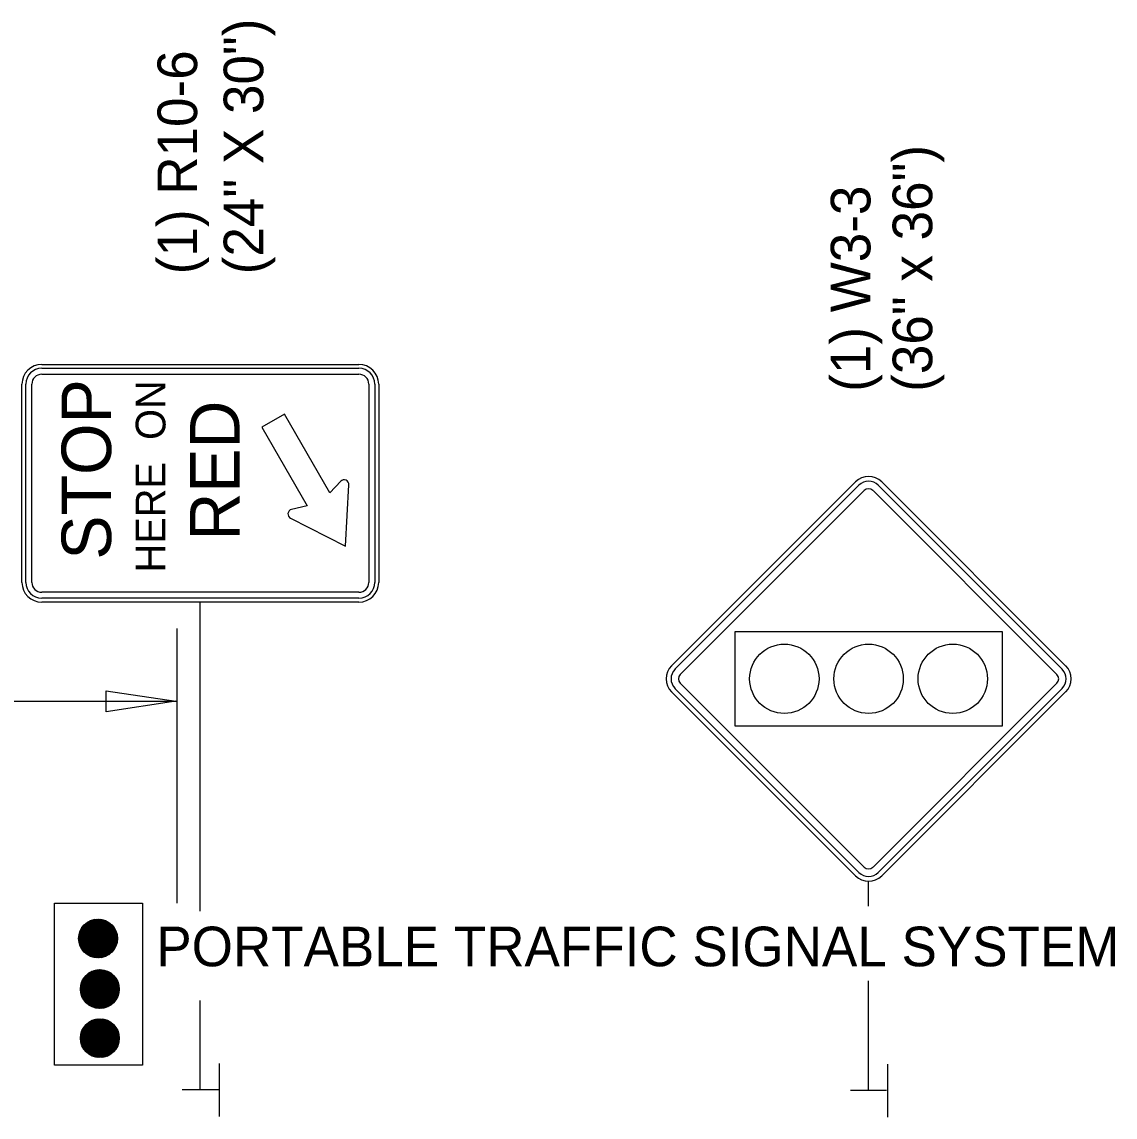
# Model space of a CAD drawing. Extents: x 1926586 to 1930787, y 596452 to 599566.
# Drawn here: x 1928013.4 to 1928178.9, y 598956.9 to 599122.6 of the extents above; entities that cross this region are included whole.
import ezdxf

# ---------------------------------------------------------------- set-up
doc = ezdxf.new("R2010")
doc.units = 0
for name, color, linetype in [('Default', 7, 'Continuous'), ('P_TC_Signs_Permanent', 7, 'Continuous'), ('R_Border', 7, 'Continuous')]:
    doc.layers.add(name, color=color, linetype=linetype)

msp = doc.modelspace()

# ---------------------------------------------------------------- linework, layer by layer
at = {"layer": 'Default'}
for p, q in [((1928036.82, 599030.83), (1928036.82, 598989.25)), ((1928026.16, 599018.22), (1928026.16, 599021.38)), ((1928026.16, 599021.38), (1928036.71, 599019.8)), ((1927973.15, 599019.8), (1928036.82, 599019.8)), ((1928036.71, 599019.8), (1928026.16, 599018.22)), ((1928021.98, 598983.77), (1928025.06, 598986.84)), ((1928021.98, 598983.94), (1928024.88, 598986.84)), ((1928021.99, 598984.13), (1928024.69, 598986.83)), ((1928022, 598983.6), (1928025.23, 598986.83)), ((1928022.01, 598984.34), (1928024.49, 598986.81)), ((1928022.02, 598983.44), (1928025.39, 598986.81)), ((1928022.05, 598983.29), (1928025.54, 598986.78)), ((1928022.06, 598984.56), (1928024.26, 598986.77)), ((1928022.08, 598983.14), (1928025.68, 598986.74)), ((1928022.12, 598983), (1928025.82, 598986.7)), ((1928022.12, 598984.81), (1928024.01, 598986.7)), ((1928022.17, 598982.87), (1928025.96, 598986.66)), ((1928022.22, 598982.74), (1928026.09, 598986.6)), ((1928022.24, 598985.11), (1928023.72, 598986.59)), ((1928022.28, 598982.61), (1928026.21, 598986.55)), ((1928022.34, 598982.49), (1928026.33, 598986.48)), ((1928022.41, 598982.38), (1928026.45, 598986.42)), ((1928022.46, 598985.5), (1928023.32, 598986.37)), ((1928022.48, 598982.27), (1928026.56, 598986.35)), ((1928022.55, 598982.16), (1928026.66, 598986.27)), ((1928022.63, 598982.06), (1928026.76, 598986.2)), ((1928022.71, 598981.96), (1928026.86, 598986.11)), ((1928022.8, 598981.87), (1928026.96, 598986.03)), ((1928022.89, 598981.78), (1928027.05, 598985.94)), ((1928022.98, 598981.69), (1928027.13, 598985.84)), ((1928023.08, 598981.61), (1928027.22, 598985.74)), ((1928023.18, 598981.53), (1928027.3, 598985.64)), ((1928023.29, 598981.45), (1928027.37, 598985.53)), ((1928023.4, 598981.38), (1928027.44, 598985.42)), ((1928023.52, 598981.32), (1928027.51, 598985.31)), ((1928023.63, 598981.26), (1928027.57, 598985.19)), ((1928023.76, 598981.2), (1928027.62, 598985.07)), ((1928023.89, 598981.15), (1928027.68, 598984.94)), ((1928024.02, 598981.1), (1928027.72, 598984.8)), ((1928024.16, 598981.06), (1928027.76, 598984.66)), ((1928024.31, 598981.03), (1928027.8, 598984.52)), ((1928024.46, 598981), (1928027.83, 598984.36)), ((1928024.62, 598980.98), (1928027.85, 598984.2)), ((1928024.79, 598980.96), (1928027.86, 598984.04)), ((1928024.97, 598980.96), (1928027.86, 598983.86)), ((1928025.16, 598980.97), (1928027.85, 598983.67)), ((1928025.36, 598980.99), (1928027.83, 598983.46)), ((1928025.58, 598981.04), (1928027.79, 598983.24)), ((1928025.83, 598981.11), (1928027.72, 598982.99)), ((1928026.13, 598981.22), (1928027.6, 598982.69)), ((1928026.53, 598981.44), (1928027.39, 598982.3)), ((1928022.25, 598976.11), (1928025.33, 598979.18)), ((1928022.25, 598976.29), (1928025.15, 598979.18)), ((1928022.26, 598976.47), (1928024.96, 598979.18)), ((1928022.27, 598975.94), (1928025.5, 598979.17)), ((1928022.28, 598976.68), (1928024.76, 598979.15)), ((1928022.29, 598975.78), (1928025.66, 598979.15)), ((1928022.32, 598975.63), (1928025.81, 598979.12)), ((1928022.32, 598976.9), (1928024.53, 598979.11)), ((1928022.35, 598975.48), (1928025.95, 598979.08)), ((1928022.39, 598975.34), (1928026.09, 598979.04)), ((1928022.39, 598977.15), (1928024.28, 598979.04)), ((1928022.44, 598975.21), (1928026.23, 598979)), ((1928022.49, 598975.08), (1928026.36, 598978.94)), ((1928022.51, 598977.45), (1928023.99, 598978.93)), ((1928022.55, 598974.95), (1928026.48, 598978.89)), ((1928022.61, 598974.83), (1928026.6, 598978.83)), ((1928022.67, 598974.72), (1928026.71, 598978.76)), ((1928022.72, 598977.84), (1928023.59, 598978.71)), ((1928022.75, 598974.61), (1928026.82, 598978.69)), ((1928022.82, 598974.5), (1928026.93, 598978.61)), ((1928022.9, 598974.4), (1928027.03, 598978.54)), ((1928022.98, 598974.3), (1928027.13, 598978.45)), ((1928023.07, 598974.21), (1928027.23, 598978.37)), ((1928023.16, 598974.12), (1928027.32, 598978.28)), ((1928023.25, 598974.03), (1928027.4, 598978.18)), ((1928023.35, 598973.95), (1928027.49, 598978.08)), ((1928023.45, 598973.87), (1928027.56, 598977.98)), ((1928023.56, 598973.8), (1928027.64, 598977.87)), ((1928023.67, 598973.73), (1928027.71, 598977.76)), ((1928023.78, 598973.66), (1928027.78, 598977.65)), ((1928023.9, 598973.6), (1928027.84, 598977.53)), ((1928024.03, 598973.54), (1928027.89, 598977.41)), ((1928024.16, 598973.49), (1928027.95, 598977.28)), ((1928024.29, 598973.44), (1928027.99, 598977.14)), ((1928024.43, 598973.4), (1928028.03, 598977)), ((1928024.58, 598973.37), (1928028.07, 598976.86)), ((1928024.73, 598973.34), (1928028.1, 598976.7)), ((1928024.89, 598973.32), (1928028.12, 598976.55)), ((1928025.06, 598973.3), (1928028.13, 598976.38)), ((1928025.24, 598973.3), (1928028.13, 598976.2)), ((1928025.43, 598973.31), (1928028.12, 598976.01)), ((1928025.63, 598973.33), (1928028.1, 598975.8)), ((1928025.85, 598973.38), (1928028.06, 598975.58)), ((1928026.1, 598973.45), (1928027.99, 598975.33)), ((1928026.4, 598973.56), (1928027.87, 598975.04)), ((1928026.8, 598973.78), (1928027.66, 598974.64)), ((1928022.25, 598968.77), (1928025.23, 598971.74)), ((1928022.25, 598968.95), (1928025.04, 598971.74)), ((1928022.26, 598968.59), (1928025.4, 598971.74)), ((1928022.27, 598969.15), (1928024.85, 598971.73)), ((1928022.27, 598968.43), (1928025.57, 598971.72)), ((1928022.3, 598968.27), (1928025.72, 598971.7)), ((1928022.3, 598969.36), (1928024.63, 598971.69)), ((1928022.33, 598968.12), (1928025.87, 598971.67)), ((1928022.36, 598969.6), (1928024.4, 598971.64)), ((1928022.37, 598967.98), (1928026.02, 598971.63)), ((1928022.41, 598967.84), (1928026.15, 598971.58)), ((1928022.45, 598969.87), (1928024.12, 598971.54)), ((1928022.46, 598967.71), (1928026.29, 598971.53)), ((1928022.51, 598967.58), (1928026.41, 598971.48)), ((1928022.57, 598967.46), (1928026.53, 598971.42)), ((1928022.61, 598970.21), (1928023.79, 598971.39)), ((1928022.64, 598967.34), (1928026.65, 598971.36)), ((1928022.71, 598967.23), (1928026.76, 598971.29)), ((1928022.78, 598967.12), (1928026.87, 598971.22)), ((1928022.85, 598967.02), (1928026.98, 598971.14)), ((1928022.93, 598966.92), (1928027.08, 598971.06)), ((1928023.02, 598966.82), (1928027.17, 598970.98)), ((1928023.11, 598966.73), (1928027.27, 598970.89)), ((1928023.2, 598966.64), (1928027.36, 598970.8)), ((1928023.3, 598966.55), (1928027.44, 598970.7)), ((1928023.4, 598966.47), (1928027.52, 598970.6)), ((1928023.5, 598966.4), (1928027.6, 598970.5)), ((1928023.61, 598966.32), (1928027.67, 598970.39)), ((1928023.72, 598966.26), (1928027.74, 598970.27)), ((1928023.84, 598966.19), (1928027.8, 598970.16)), ((1928023.96, 598966.13), (1928027.86, 598970.04)), ((1928024.08, 598966.08), (1928027.92, 598969.91)), ((1928024.22, 598966.03), (1928027.97, 598969.78)), ((1928024.35, 598965.98), (1928028.01, 598969.64)), ((1928024.49, 598965.95), (1928028.05, 598969.5)), ((1928024.64, 598965.91), (1928028.08, 598969.35)), ((1928024.8, 598965.89), (1928028.11, 598969.2)), ((1928024.96, 598965.87), (1928028.12, 598969.03)), ((1928025.14, 598965.86), (1928028.13, 598968.86)), ((1928025.32, 598965.86), (1928028.13, 598968.68)), ((1928025.51, 598965.88), (1928028.12, 598968.48)), ((1928025.73, 598965.91), (1928028.08, 598968.27)), ((1928025.96, 598965.96), (1928028.03, 598968.03)), ((1928026.23, 598966.05), (1928027.94, 598967.77)), ((1928026.55, 598966.2), (1928027.8, 598967.44)), ((1928027.13, 598966.59), (1928027.41, 598966.87)), ((1928043.25, 598964.97), (1928043.25, 598956.96)), ((1928144.39, 598964.87), (1928144.39, 598956.86)), ((1928043.13, 598960.99), (1928037.66, 598960.99)), ((1928144.27, 598960.89), (1928138.81, 598960.89))]:
    msp.add_line(p, q, dxfattribs=at)
msp.add_lwpolyline([(1928018.35, 598989.25), (1928031.64, 598989.25), (1928031.64, 598964.72), (1928018.35, 598964.72)], close=True, dxfattribs=at)
for centre in [(1928024.92, 598983.9), (1928025.19, 598976.24), (1928025.19, 598968.8)]:
    msp.add_circle(centre, 2.94, dxfattribs=at)
at = {"layer": 'P_TC_Signs_Permanent'}
for p, q in [((1928016.4, 599070.8), (1928064.4, 599070.8)), ((1928016.4, 599070.2), (1928064.4, 599070.2)), ((1928016.4, 599069.3), (1928064.4, 599069.3)), ((1928013.4, 599037.8), (1928013.4, 599067.8)), ((1928014, 599037.8), (1928014, 599067.8)), ((1928014.9, 599037.8), (1928014.9, 599067.8)), ((1928065.9, 599067.8), (1928065.9, 599037.8)), ((1928066.8, 599067.8), (1928066.8, 599037.8)), ((1928067.4, 599067.8), (1928067.4, 599037.8)), ((1928111.71, 599025.19), (1928139.55, 599053.03)), ((1928143.53, 599053.03), (1928171.37, 599025.19)), ((1928112.24, 599024.66), (1928140.08, 599052.5)), ((1928140.88, 599051.7), (1928113.04, 599023.86)), ((1928170.05, 599023.86), (1928142.21, 599051.7)), ((1928143, 599052.5), (1928170.84, 599024.66)), ((1928064.4, 599036.3), (1928016.4, 599036.3)), ((1928064.4, 599035.4), (1928016.4, 599035.4)), ((1928064.4, 599034.8), (1928016.4, 599034.8)), ((1928139.55, 598993.37), (1928111.71, 599021.21)), ((1928140.08, 598993.9), (1928112.24, 599021.74)), ((1928113.04, 599022.54), (1928140.88, 598994.69)), ((1928142.21, 598994.69), (1928170.05, 599022.54)), ((1928170.84, 599021.74), (1928143, 598993.9)), ((1928171.37, 599021.21), (1928143.53, 598993.37))]:
    msp.add_line(p, q, dxfattribs=at)
for points in [[(1928061.65, 599053.1), (1928060, 599051.36), (1928053.12, 599063.28), (1928049.71, 599061.31), (1928056.59, 599049.39), (1928054.22, 599048.84)], [(1928054.06, 599047.5), (1928062.38, 599043.3), (1928062.89, 599052.57)]]:
    msp.add_lwpolyline(points, dxfattribs=at)
msp.add_lwpolyline([(1928161.79, 599016.07), (1928161.79, 599030.32), (1928121.29, 599030.32), (1928121.29, 599016.07)], close=True, dxfattribs=at)
for centre in [(1928128.79, 599023.2), (1928141.54, 599023.2), (1928154.29, 599023.2)]:
    msp.add_circle(centre, 5.25, dxfattribs=at)
for centre, radius, start, end in [((1928016.4, 599067.8), 3, 90, 180), ((1928064.4, 599067.8), 3, 360, 90), ((1928016.4, 599067.8), 2.4, 90, 180), ((1928016.4, 599067.8), 1.5, 90, 180), ((1928064.4, 599067.8), 2.4, 360, 90), ((1928064.4, 599067.8), 1.5, 360, 90), ((1928062.17, 599052.61), 0.72, 356.857, 136.6377), ((1928141.54, 599051.04), 2.81, 45, 135), ((1928141.54, 599051.04), 2.06, 45, 135), ((1928141.54, 599051.04), 0.938, 45, 135), ((1928054.38, 599048.14), 0.72, 103.0349, 243.2286), ((1928016.4, 599037.8), 3, 180, 270), ((1928016.4, 599037.8), 2.4, 180, 270), ((1928016.4, 599037.8), 1.5, 180, 270), ((1928064.4, 599037.8), 3, 270, 360), ((1928064.4, 599037.8), 2.4, 270, 360), ((1928064.4, 599037.8), 1.5, 270, 360), ((1928113.7, 599023.2), 2.81, 135, 225), ((1928113.7, 599023.2), 2.06, 135, 225), ((1928169.39, 599023.2), 2.06, 315, 45), ((1928169.39, 599023.2), 2.81, 315, 45), ((1928113.7, 599023.2), 0.938, 135, 225), ((1928169.39, 599023.2), 0.938, 315, 45), ((1928141.54, 598995.36), 0.938, 225, 315), ((1928141.54, 598995.36), 2.81, 225, 315), ((1928141.54, 598995.36), 2.06, 225, 315)]:
    msp.add_arc(centre, radius, start, end, dxfattribs=at)
at = {"layer": 'R_Border'}
for p, q in [((1928040.4, 598988.05), (1928040.4, 599034.8)), ((1928141.54, 598988.78), (1928141.54, 598992.54)), ((1928141.54, 598960.89), (1928141.54, 598977.5)), ((1928040.4, 598960.99), (1928040.4, 598974.52))]:
    msp.add_line(p, q, dxfattribs=at)

# ---------------------------------------------------------------- texts
at = {"layer": 'Default'}
msp.add_text('PORTABLE TRAFFIC SIGNAL SYSTEM', height=5.9996, rotation=360, dxfattribs=at).set_placement((1928033.74, 598979.69))
at = {"layer": 'P_TC_Signs_Permanent'}
for s, height, p in [('STOP', 7.5, (1928026.9, 599041.24)), ('HERE  ON', 4.5, (1928035.12, 599039.3)), ('RED', 7.5, (1928046.34, 599044.13))]:
    msp.add_text(s, height=height, rotation=90, dxfattribs=at).set_placement(p)
at = {"layer": 'R_Border'}
for s, height, p in [('(24" X 30")', 5.9996, (1928049.93, 599084.44)), ('(1) R10-6', 6, (1928039.92, 599084.44)), ('(36" x 36")', 5.9996, (1928151.18, 599066.65)), ('(1) W3-3', 6, (1928141.82, 599066.65))]:
    msp.add_text(s, height=height, rotation=90, dxfattribs=at).set_placement(p)

doc.saveas('drawing.dxf')
